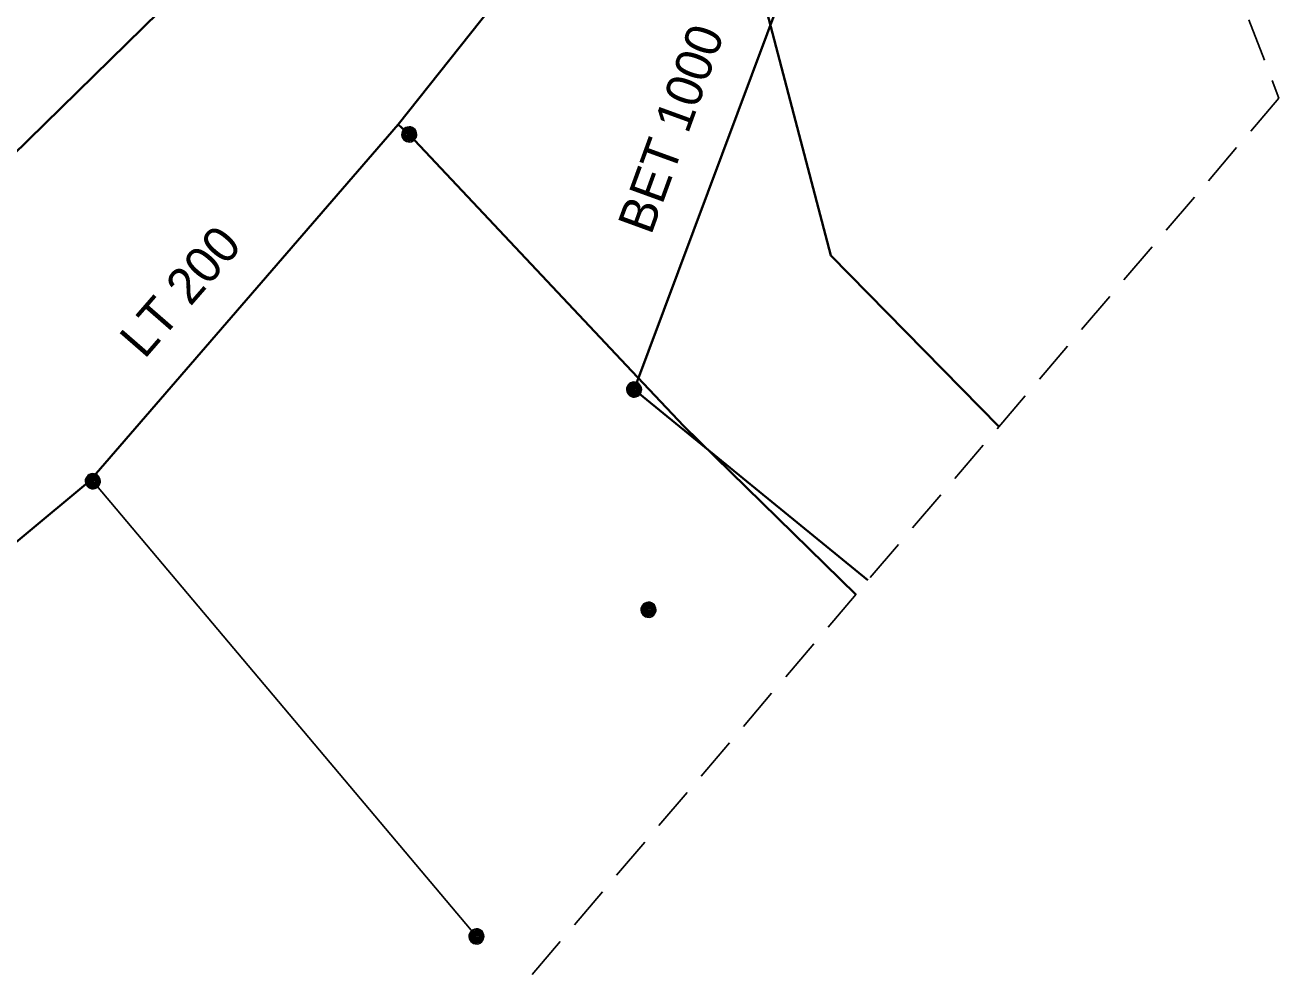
# Model space of a CAD drawing. Extents: x -867104 to -866746, y -1014489 to -1014255.
# Drawn here: x -866784.33 to -866746.24, y -1014389.22 to -1014360.49 of the extents above; entities that cross this region are included whole.
import ezdxf

# ---------------------------------------------------------------- set-up
doc = ezdxf.new("R2010")
doc.units = 0
doc.header["$LTSCALE"] = 0.44
doc.linetypes.add('MEDIUM_DASHED', pattern=[4.5, 3, -1.5])
for name, color, linetype, lineweight in [('1', 7, 'Continuous', 35), ('10', 7, 'Continuous', 13), ('12', 7, 'Continuous', 13), ('21', 7, 'Continuous', 35), ('3', 7, 'Continuous', 25), ('32', 7, 'Continuous', 13), ('62', 7, 'MEDIUM_DASHED', 25)]:
    doc.layers.add(name, color=color, linetype=linetype, lineweight=lineweight)

msp = doc.modelspace()

# ---------------------------------------------------------------- linework, layer by layer
at = {"layer": '1'}
for points in [[(-866752.928, -1014345.35), (-866767.662, -1014356.784), (-866772.99, -1014363.51), (-866782.36, -1014374.33), (-866829.29, -1014413.39)], [(-866763.454, -1014353.518), (-866763.39, -1014353.97), (-866759.847, -1014367.488), (-866754.744, -1014372.687)], [(-866772.99, -1014363.51), (-866772.66, -1014363.81), (-866765.9, -1014371), (-866764.32, -1014372.67), (-866759.089, -1014377.786)]]:
    msp.add_lwpolyline(points, dxfattribs=at)
at = {"layer": '10'}
for points in [[(-866770.385, -1014388.173), (-866770.391, -1014388.121), (-866770.408, -1014388.071), (-866770.437, -1014388.027), (-866770.474, -1014387.99), (-866770.519, -1014387.963), (-866770.569, -1014387.946), (-866770.622, -1014387.942), (-866770.674, -1014387.949), (-866770.723, -1014387.968), (-866770.766, -1014387.997), (-866770.802, -1014388.036), (-866770.828, -1014388.081), (-866770.844, -1014388.132), (-866770.847, -1014388.184), (-866770.839, -1014388.236), (-866770.819, -1014388.285), (-866770.788, -1014388.328), (-866770.749, -1014388.362), (-866770.703, -1014388.388), (-866770.652, -1014388.402), (-866770.599, -1014388.404), (-866770.548, -1014388.394), (-866770.5, -1014388.373), (-866770.457, -1014388.342), (-866770.423, -1014388.301), (-866770.399, -1014388.255), (-866770.387, -1014388.204)], [(-866770.415, -1014388.173), (-866770.421, -1014388.124), (-866770.438, -1014388.078), (-866770.466, -1014388.038), (-866770.503, -1014388.006), (-866770.547, -1014387.984), (-866770.595, -1014387.973), (-866770.644, -1014387.973), (-866770.691, -1014387.986), (-866770.734, -1014388.01), (-866770.77, -1014388.043), (-866770.797, -1014388.084), (-866770.813, -1014388.131), (-866770.817, -1014388.18), (-866770.81, -1014388.228), (-866770.791, -1014388.273), (-866770.761, -1014388.313), (-866770.723, -1014388.344), (-866770.679, -1014388.364), (-866770.631, -1014388.374), (-866770.582, -1014388.372), (-866770.535, -1014388.357), (-866770.492, -1014388.332), (-866770.458, -1014388.298), (-866770.432, -1014388.256), (-866770.418, -1014388.209)], [(-866770.445, -1014388.173), (-866770.451, -1014388.128), (-866770.468, -1014388.086), (-866770.496, -1014388.051), (-866770.532, -1014388.024), (-866770.574, -1014388.007), (-866770.619, -1014388.002), (-866770.664, -1014388.008), (-866770.705, -1014388.027), (-866770.74, -1014388.055), (-866770.767, -1014388.092), (-866770.783, -1014388.134), (-866770.787, -1014388.179), (-866770.78, -1014388.224), (-866770.761, -1014388.265), (-866770.732, -1014388.299), (-866770.695, -1014388.325), (-866770.652, -1014388.341), (-866770.607, -1014388.344), (-866770.562, -1014388.336), (-866770.522, -1014388.316), (-866770.488, -1014388.287), (-866770.462, -1014388.249), (-866770.448, -1014388.206)], [(-866770.475, -1014388.173), (-866770.48, -1014388.132), (-866770.498, -1014388.095), (-866770.525, -1014388.064), (-866770.56, -1014388.043), (-866770.6, -1014388.032), (-866770.641, -1014388.034), (-866770.68, -1014388.047), (-866770.714, -1014388.071), (-866770.739, -1014388.103), (-866770.754, -1014388.141), (-866770.757, -1014388.182), (-866770.749, -1014388.222), (-866770.729, -1014388.258), (-866770.7, -1014388.287), (-866770.663, -1014388.306), (-866770.623, -1014388.314), (-866770.582, -1014388.31), (-866770.544, -1014388.295), (-866770.512, -1014388.269), (-866770.489, -1014388.235), (-866770.476, -1014388.196)], [(-866770.505, -1014388.173), (-866770.51, -1014388.137), (-866770.528, -1014388.105), (-866770.554, -1014388.08), (-866770.588, -1014388.065), (-866770.624, -1014388.062), (-866770.659, -1014388.07), (-866770.69, -1014388.09), (-866770.713, -1014388.118), (-866770.726, -1014388.152), (-866770.726, -1014388.189), (-866770.715, -1014388.224), (-866770.694, -1014388.253), (-866770.664, -1014388.274), (-866770.629, -1014388.284), (-866770.592, -1014388.282), (-866770.558, -1014388.268), (-866770.531, -1014388.245), (-866770.512, -1014388.213), (-866770.505, -1014388.178)], [(-866770.535, -1014388.173), (-866770.54, -1014388.142), (-866770.557, -1014388.116), (-866770.583, -1014388.099), (-866770.613, -1014388.092), (-866770.644, -1014388.096), (-866770.671, -1014388.113), (-866770.689, -1014388.137), (-866770.697, -1014388.168), (-866770.693, -1014388.198), (-866770.678, -1014388.226), (-866770.654, -1014388.245), (-866770.624, -1014388.254), (-866770.593, -1014388.251), (-866770.565, -1014388.237), (-866770.545, -1014388.213), (-866770.535, -1014388.184)], [(-866770.565, -1014388.173), (-866770.57, -1014388.149), (-866770.587, -1014388.131), (-866770.61, -1014388.122), (-866770.634, -1014388.125), (-866770.655, -1014388.139), (-866770.666, -1014388.161), (-866770.666, -1014388.186), (-866770.654, -1014388.207), (-866770.634, -1014388.221), (-866770.609, -1014388.224), (-866770.586, -1014388.215), (-866770.57, -1014388.197)], [(-866770.595, -1014388.173), (-866770.6, -1014388.158), (-866770.615, -1014388.152), (-866770.63, -1014388.156), (-866770.637, -1014388.17), (-866770.633, -1014388.185), (-866770.62, -1014388.194), (-866770.605, -1014388.191), (-866770.595, -1014388.179)]]:
    msp.add_lwpolyline(points, close=True, dxfattribs=at)
at = {"layer": '12'}
for points in [[(-866772.428, -1014363.81), (-866772.434, -1014363.758), (-866772.451, -1014363.708), (-866772.48, -1014363.664), (-866772.517, -1014363.627), (-866772.562, -1014363.6), (-866772.612, -1014363.583), (-866772.665, -1014363.579), (-866772.717, -1014363.586), (-866772.766, -1014363.605), (-866772.809, -1014363.634), (-866772.845, -1014363.673), (-866772.871, -1014363.718), (-866772.887, -1014363.769), (-866772.89, -1014363.821), (-866772.882, -1014363.873), (-866772.862, -1014363.922), (-866772.831, -1014363.965), (-866772.792, -1014363.999), (-866772.746, -1014364.025), (-866772.695, -1014364.039), (-866772.642, -1014364.041), (-866772.591, -1014364.031), (-866772.543, -1014364.01), (-866772.5, -1014363.979), (-866772.466, -1014363.938), (-866772.442, -1014363.892), (-866772.429, -1014363.841)], [(-866772.458, -1014363.81), (-866772.464, -1014363.761), (-866772.481, -1014363.715), (-866772.509, -1014363.675), (-866772.546, -1014363.643), (-866772.59, -1014363.621), (-866772.638, -1014363.61), (-866772.687, -1014363.61), (-866772.733, -1014363.623), (-866772.777, -1014363.647), (-866772.813, -1014363.68), (-866772.84, -1014363.721), (-866772.856, -1014363.768), (-866772.86, -1014363.817), (-866772.853, -1014363.865), (-866772.834, -1014363.91), (-866772.804, -1014363.95), (-866772.766, -1014363.981), (-866772.722, -1014364.001), (-866772.674, -1014364.011), (-866772.625, -1014364.009), (-866772.578, -1014363.994), (-866772.535, -1014363.969), (-866772.5, -1014363.935), (-866772.475, -1014363.893), (-866772.461, -1014363.846)], [(-866772.488, -1014363.81), (-866772.494, -1014363.765), (-866772.511, -1014363.723), (-866772.539, -1014363.688), (-866772.575, -1014363.661), (-866772.617, -1014363.644), (-866772.662, -1014363.639), (-866772.706, -1014363.645), (-866772.748, -1014363.664), (-866772.782, -1014363.692), (-866772.809, -1014363.729), (-866772.826, -1014363.771), (-866772.83, -1014363.816), (-866772.823, -1014363.861), (-866772.804, -1014363.902), (-866772.775, -1014363.936), (-866772.738, -1014363.962), (-866772.695, -1014363.978), (-866772.65, -1014363.981), (-866772.605, -1014363.973), (-866772.565, -1014363.953), (-866772.531, -1014363.924), (-866772.505, -1014363.886), (-866772.491, -1014363.843)], [(-866772.518, -1014363.81), (-866772.522, -1014363.769), (-866772.541, -1014363.732), (-866772.568, -1014363.701), (-866772.603, -1014363.68), (-866772.643, -1014363.669), (-866772.684, -1014363.671), (-866772.723, -1014363.684), (-866772.757, -1014363.708), (-866772.782, -1014363.74), (-866772.797, -1014363.778), (-866772.799, -1014363.819), (-866772.792, -1014363.859), (-866772.772, -1014363.895), (-866772.743, -1014363.924), (-866772.706, -1014363.943), (-866772.666, -1014363.951), (-866772.625, -1014363.947), (-866772.587, -1014363.932), (-866772.554, -1014363.906), (-866772.532, -1014363.872), (-866772.519, -1014363.833)], [(-866772.548, -1014363.81), (-866772.553, -1014363.774), (-866772.571, -1014363.742), (-866772.597, -1014363.717), (-866772.63, -1014363.702), (-866772.667, -1014363.699), (-866772.701, -1014363.707), (-866772.733, -1014363.727), (-866772.755, -1014363.755), (-866772.769, -1014363.789), (-866772.769, -1014363.826), (-866772.758, -1014363.861), (-866772.737, -1014363.89), (-866772.706, -1014363.911), (-866772.672, -1014363.921), (-866772.635, -1014363.919), (-866772.601, -1014363.905), (-866772.574, -1014363.882), (-866772.554, -1014363.85), (-866772.548, -1014363.815)], [(-866772.578, -1014363.81), (-866772.583, -1014363.779), (-866772.6, -1014363.753), (-866772.625, -1014363.736), (-866772.656, -1014363.729), (-866772.687, -1014363.733), (-866772.714, -1014363.75), (-866772.732, -1014363.774), (-866772.74, -1014363.805), (-866772.736, -1014363.835), (-866772.721, -1014363.863), (-866772.696, -1014363.882), (-866772.667, -1014363.891), (-866772.636, -1014363.888), (-866772.608, -1014363.874), (-866772.588, -1014363.85), (-866772.578, -1014363.821)], [(-866772.608, -1014363.81), (-866772.613, -1014363.786), (-866772.63, -1014363.768), (-866772.652, -1014363.759), (-866772.677, -1014363.762), (-866772.698, -1014363.776), (-866772.709, -1014363.798), (-866772.709, -1014363.823), (-866772.696, -1014363.844), (-866772.677, -1014363.858), (-866772.652, -1014363.861), (-866772.629, -1014363.852), (-866772.613, -1014363.834)], [(-866772.638, -1014363.81), (-866772.643, -1014363.795), (-866772.657, -1014363.789), (-866772.673, -1014363.793), (-866772.679, -1014363.807), (-866772.676, -1014363.822), (-866772.663, -1014363.831), (-866772.647, -1014363.828), (-866772.638, -1014363.816)], [(-866782.041, -1014374.344), (-866782.047, -1014374.292), (-866782.064, -1014374.242), (-866782.093, -1014374.198), (-866782.13, -1014374.161), (-866782.175, -1014374.134), (-866782.225, -1014374.117), (-866782.278, -1014374.113), (-866782.33, -1014374.12), (-866782.379, -1014374.139), (-866782.422, -1014374.168), (-866782.458, -1014374.207), (-866782.484, -1014374.252), (-866782.5, -1014374.303), (-866782.503, -1014374.355), (-866782.495, -1014374.407), (-866782.475, -1014374.456), (-866782.444, -1014374.499), (-866782.405, -1014374.533), (-866782.359, -1014374.559), (-866782.308, -1014374.573), (-866782.255, -1014374.575), (-866782.204, -1014374.565), (-866782.156, -1014374.544), (-866782.113, -1014374.513), (-866782.079, -1014374.472), (-866782.055, -1014374.426), (-866782.043, -1014374.375)], [(-866782.071, -1014374.344), (-866782.077, -1014374.295), (-866782.094, -1014374.249), (-866782.122, -1014374.209), (-866782.159, -1014374.177), (-866782.203, -1014374.155), (-866782.251, -1014374.144), (-866782.3, -1014374.144), (-866782.347, -1014374.157), (-866782.39, -1014374.181), (-866782.426, -1014374.214), (-866782.453, -1014374.255), (-866782.469, -1014374.302), (-866782.473, -1014374.351), (-866782.466, -1014374.399), (-866782.447, -1014374.444), (-866782.417, -1014374.484), (-866782.379, -1014374.515), (-866782.335, -1014374.535), (-866782.287, -1014374.545), (-866782.238, -1014374.543), (-866782.191, -1014374.528), (-866782.148, -1014374.503), (-866782.114, -1014374.469), (-866782.088, -1014374.427), (-866782.074, -1014374.38)], [(-866782.101, -1014374.344), (-866782.107, -1014374.299), (-866782.124, -1014374.257), (-866782.152, -1014374.222), (-866782.188, -1014374.195), (-866782.23, -1014374.178), (-866782.275, -1014374.173), (-866782.32, -1014374.179), (-866782.361, -1014374.198), (-866782.396, -1014374.226), (-866782.423, -1014374.263), (-866782.439, -1014374.305), (-866782.443, -1014374.35), (-866782.436, -1014374.395), (-866782.417, -1014374.436), (-866782.388, -1014374.47), (-866782.351, -1014374.496), (-866782.308, -1014374.512), (-866782.263, -1014374.515), (-866782.218, -1014374.507), (-866782.178, -1014374.487), (-866782.144, -1014374.458), (-866782.118, -1014374.42), (-866782.104, -1014374.377)], [(-866782.131, -1014374.344), (-866782.136, -1014374.303), (-866782.154, -1014374.266), (-866782.181, -1014374.235), (-866782.216, -1014374.214), (-866782.256, -1014374.203), (-866782.297, -1014374.205), (-866782.336, -1014374.218), (-866782.37, -1014374.242), (-866782.395, -1014374.274), (-866782.41, -1014374.312), (-866782.413, -1014374.353), (-866782.405, -1014374.393), (-866782.385, -1014374.429), (-866782.356, -1014374.458), (-866782.319, -1014374.477), (-866782.279, -1014374.485), (-866782.238, -1014374.481), (-866782.2, -1014374.466), (-866782.168, -1014374.44), (-866782.145, -1014374.406), (-866782.132, -1014374.367)], [(-866782.161, -1014374.344), (-866782.166, -1014374.308), (-866782.184, -1014374.276), (-866782.21, -1014374.251), (-866782.244, -1014374.236), (-866782.28, -1014374.233), (-866782.315, -1014374.241), (-866782.346, -1014374.261), (-866782.369, -1014374.289), (-866782.382, -1014374.323), (-866782.382, -1014374.36), (-866782.371, -1014374.395), (-866782.35, -1014374.424), (-866782.32, -1014374.445), (-866782.285, -1014374.455), (-866782.248, -1014374.453), (-866782.214, -1014374.439), (-866782.187, -1014374.416), (-866782.168, -1014374.384), (-866782.161, -1014374.349)], [(-866782.191, -1014374.344), (-866782.196, -1014374.313), (-866782.213, -1014374.287), (-866782.239, -1014374.27), (-866782.269, -1014374.263), (-866782.3, -1014374.267), (-866782.327, -1014374.284), (-866782.345, -1014374.308), (-866782.353, -1014374.339), (-866782.349, -1014374.369), (-866782.334, -1014374.397), (-866782.309, -1014374.416), (-866782.28, -1014374.425), (-866782.249, -1014374.422), (-866782.221, -1014374.408), (-866782.201, -1014374.384), (-866782.191, -1014374.355)], [(-866782.221, -1014374.344), (-866782.226, -1014374.32), (-866782.243, -1014374.302), (-866782.266, -1014374.293), (-866782.29, -1014374.296), (-866782.311, -1014374.31), (-866782.322, -1014374.332), (-866782.322, -1014374.357), (-866782.309, -1014374.378), (-866782.29, -1014374.392), (-866782.265, -1014374.395), (-866782.242, -1014374.386), (-866782.226, -1014374.368)], [(-866782.251, -1014374.344), (-866782.256, -1014374.329), (-866782.271, -1014374.323), (-866782.286, -1014374.327), (-866782.293, -1014374.341), (-866782.289, -1014374.356), (-866782.276, -1014374.365), (-866782.261, -1014374.362), (-866782.251, -1014374.35)]]:
    msp.add_lwpolyline(points, close=True, dxfattribs=at)
at = {"layer": '21'}
for p, q in [((-866771.588, -1014351.589), (-866821.947, -1014400.93)), ((-866765.827, -1014371.56), (-866759.561, -1014354.793)), ((-866758.722, -1014377.355), (-866765.827, -1014371.56))]:
    msp.add_line(p, q, dxfattribs=at)
at = {"layer": '3'}
msp.add_line((-866782.321, -1014374.285), (-866770.616, -1014388.173), dxfattribs=at)
at = {"layer": '32'}
for points in [[(-866765.596, -1014371.56), (-866765.602, -1014371.508), (-866765.619, -1014371.458), (-866765.648, -1014371.414), (-866765.685, -1014371.377), (-866765.73, -1014371.35), (-866765.78, -1014371.333), (-866765.833, -1014371.329), (-866765.885, -1014371.336), (-866765.934, -1014371.355), (-866765.977, -1014371.384), (-866766.013, -1014371.423), (-866766.039, -1014371.468), (-866766.055, -1014371.519), (-866766.058, -1014371.571), (-866766.05, -1014371.623), (-866766.03, -1014371.672), (-866765.999, -1014371.715), (-866765.96, -1014371.749), (-866765.914, -1014371.775), (-866765.863, -1014371.789), (-866765.81, -1014371.791), (-866765.759, -1014371.781), (-866765.711, -1014371.76), (-866765.668, -1014371.729), (-866765.634, -1014371.688), (-866765.61, -1014371.642), (-866765.598, -1014371.591)], [(-866765.626, -1014371.56), (-866765.632, -1014371.511), (-866765.649, -1014371.465), (-866765.677, -1014371.425), (-866765.714, -1014371.393), (-866765.758, -1014371.371), (-866765.806, -1014371.36), (-866765.855, -1014371.36), (-866765.902, -1014371.373), (-866765.945, -1014371.397), (-866765.981, -1014371.43), (-866766.008, -1014371.471), (-866766.024, -1014371.518), (-866766.028, -1014371.567), (-866766.021, -1014371.615), (-866766.002, -1014371.66), (-866765.972, -1014371.7), (-866765.934, -1014371.731), (-866765.89, -1014371.751), (-866765.842, -1014371.761), (-866765.793, -1014371.759), (-866765.746, -1014371.744), (-866765.703, -1014371.719), (-866765.669, -1014371.685), (-866765.643, -1014371.643), (-866765.629, -1014371.596)], [(-866765.656, -1014371.56), (-866765.662, -1014371.515), (-866765.679, -1014371.473), (-866765.707, -1014371.438), (-866765.743, -1014371.411), (-866765.785, -1014371.394), (-866765.83, -1014371.389), (-866765.875, -1014371.395), (-866765.916, -1014371.414), (-866765.951, -1014371.442), (-866765.978, -1014371.479), (-866765.994, -1014371.521), (-866765.998, -1014371.566), (-866765.991, -1014371.611), (-866765.972, -1014371.652), (-866765.943, -1014371.686), (-866765.906, -1014371.712), (-866765.863, -1014371.728), (-866765.818, -1014371.731), (-866765.773, -1014371.723), (-866765.733, -1014371.703), (-866765.699, -1014371.674), (-866765.673, -1014371.636), (-866765.659, -1014371.593)], [(-866765.686, -1014371.56), (-866765.691, -1014371.519), (-866765.709, -1014371.482), (-866765.736, -1014371.451), (-866765.771, -1014371.43), (-866765.811, -1014371.419), (-866765.852, -1014371.421), (-866765.891, -1014371.434), (-866765.925, -1014371.458), (-866765.95, -1014371.49), (-866765.965, -1014371.528), (-866765.968, -1014371.569), (-866765.96, -1014371.609), (-866765.94, -1014371.645), (-866765.911, -1014371.674), (-866765.874, -1014371.693), (-866765.834, -1014371.701), (-866765.793, -1014371.697), (-866765.755, -1014371.682), (-866765.723, -1014371.656), (-866765.7, -1014371.622), (-866765.687, -1014371.583)], [(-866765.716, -1014371.56), (-866765.721, -1014371.524), (-866765.739, -1014371.492), (-866765.765, -1014371.467), (-866765.799, -1014371.452), (-866765.835, -1014371.449), (-866765.87, -1014371.457), (-866765.901, -1014371.477), (-866765.924, -1014371.505), (-866765.937, -1014371.539), (-866765.937, -1014371.576), (-866765.926, -1014371.611), (-866765.905, -1014371.64), (-866765.875, -1014371.661), (-866765.84, -1014371.671), (-866765.803, -1014371.669), (-866765.769, -1014371.655), (-866765.742, -1014371.632), (-866765.723, -1014371.6), (-866765.716, -1014371.565)], [(-866765.746, -1014371.56), (-866765.751, -1014371.529), (-866765.768, -1014371.503), (-866765.794, -1014371.486), (-866765.824, -1014371.479), (-866765.855, -1014371.483), (-866765.882, -1014371.5), (-866765.9, -1014371.524), (-866765.908, -1014371.555), (-866765.904, -1014371.585), (-866765.889, -1014371.613), (-866765.865, -1014371.632), (-866765.835, -1014371.641), (-866765.804, -1014371.638), (-866765.776, -1014371.624), (-866765.756, -1014371.6), (-866765.746, -1014371.571)], [(-866765.776, -1014371.56), (-866765.781, -1014371.536), (-866765.798, -1014371.518), (-866765.821, -1014371.509), (-866765.845, -1014371.512), (-866765.866, -1014371.526), (-866765.877, -1014371.548), (-866765.877, -1014371.573), (-866765.865, -1014371.594), (-866765.845, -1014371.608), (-866765.82, -1014371.611), (-866765.797, -1014371.602), (-866765.781, -1014371.584)], [(-866765.806, -1014371.56), (-866765.811, -1014371.545), (-866765.826, -1014371.539), (-866765.841, -1014371.543), (-866765.848, -1014371.557), (-866765.844, -1014371.572), (-866765.831, -1014371.581), (-866765.816, -1014371.578), (-866765.806, -1014371.566)], [(-866765.159, -1014378.25), (-866765.165, -1014378.198), (-866765.182, -1014378.148), (-866765.211, -1014378.104), (-866765.248, -1014378.067), (-866765.293, -1014378.04), (-866765.343, -1014378.023), (-866765.396, -1014378.019), (-866765.448, -1014378.026), (-866765.497, -1014378.045), (-866765.54, -1014378.074), (-866765.576, -1014378.113), (-866765.602, -1014378.158), (-866765.618, -1014378.209), (-866765.621, -1014378.261), (-866765.613, -1014378.313), (-866765.593, -1014378.362), (-866765.562, -1014378.405), (-866765.523, -1014378.439), (-866765.477, -1014378.465), (-866765.426, -1014378.479), (-866765.373, -1014378.481), (-866765.322, -1014378.471), (-866765.274, -1014378.45), (-866765.231, -1014378.419), (-866765.197, -1014378.378), (-866765.173, -1014378.332), (-866765.161, -1014378.281)], [(-866765.189, -1014378.25), (-866765.195, -1014378.201), (-866765.212, -1014378.155), (-866765.24, -1014378.115), (-866765.277, -1014378.083), (-866765.321, -1014378.061), (-866765.369, -1014378.05), (-866765.418, -1014378.05), (-866765.465, -1014378.063), (-866765.508, -1014378.087), (-866765.544, -1014378.12), (-866765.571, -1014378.161), (-866765.587, -1014378.208), (-866765.591, -1014378.257), (-866765.584, -1014378.305), (-866765.565, -1014378.35), (-866765.535, -1014378.39), (-866765.497, -1014378.421), (-866765.453, -1014378.441), (-866765.405, -1014378.451), (-866765.356, -1014378.449), (-866765.309, -1014378.434), (-866765.266, -1014378.409), (-866765.232, -1014378.375), (-866765.206, -1014378.333), (-866765.192, -1014378.286)], [(-866765.219, -1014378.25), (-866765.225, -1014378.205), (-866765.242, -1014378.163), (-866765.27, -1014378.128), (-866765.306, -1014378.101), (-866765.348, -1014378.084), (-866765.393, -1014378.079), (-866765.438, -1014378.085), (-866765.479, -1014378.104), (-866765.514, -1014378.132), (-866765.541, -1014378.169), (-866765.557, -1014378.211), (-866765.561, -1014378.256), (-866765.554, -1014378.301), (-866765.535, -1014378.342), (-866765.506, -1014378.376), (-866765.469, -1014378.402), (-866765.426, -1014378.418), (-866765.381, -1014378.421), (-866765.336, -1014378.413), (-866765.296, -1014378.393), (-866765.262, -1014378.364), (-866765.236, -1014378.326), (-866765.222, -1014378.283)], [(-866765.249, -1014378.25), (-866765.254, -1014378.209), (-866765.272, -1014378.172), (-866765.299, -1014378.141), (-866765.334, -1014378.12), (-866765.374, -1014378.109), (-866765.415, -1014378.111), (-866765.454, -1014378.124), (-866765.488, -1014378.148), (-866765.513, -1014378.18), (-866765.528, -1014378.218), (-866765.531, -1014378.259), (-866765.523, -1014378.299), (-866765.503, -1014378.335), (-866765.474, -1014378.364), (-866765.437, -1014378.383), (-866765.397, -1014378.391), (-866765.356, -1014378.387), (-866765.318, -1014378.372), (-866765.286, -1014378.346), (-866765.263, -1014378.312), (-866765.25, -1014378.273)], [(-866765.279, -1014378.25), (-866765.284, -1014378.214), (-866765.302, -1014378.182), (-866765.328, -1014378.157), (-866765.362, -1014378.142), (-866765.398, -1014378.139), (-866765.433, -1014378.147), (-866765.464, -1014378.167), (-866765.487, -1014378.195), (-866765.5, -1014378.229), (-866765.5, -1014378.266), (-866765.489, -1014378.301), (-866765.468, -1014378.33), (-866765.438, -1014378.351), (-866765.403, -1014378.361), (-866765.366, -1014378.359), (-866765.332, -1014378.345), (-866765.305, -1014378.322), (-866765.286, -1014378.29), (-866765.279, -1014378.255)], [(-866765.309, -1014378.25), (-866765.314, -1014378.219), (-866765.331, -1014378.193), (-866765.357, -1014378.176), (-866765.387, -1014378.169), (-866765.418, -1014378.173), (-866765.445, -1014378.19), (-866765.463, -1014378.214), (-866765.471, -1014378.245), (-866765.467, -1014378.275), (-866765.452, -1014378.303), (-866765.428, -1014378.322), (-866765.398, -1014378.331), (-866765.367, -1014378.328), (-866765.339, -1014378.314), (-866765.319, -1014378.29), (-866765.309, -1014378.261)], [(-866765.339, -1014378.25), (-866765.344, -1014378.226), (-866765.361, -1014378.208), (-866765.384, -1014378.199), (-866765.408, -1014378.202), (-866765.429, -1014378.216), (-866765.44, -1014378.238), (-866765.44, -1014378.263), (-866765.428, -1014378.284), (-866765.408, -1014378.298), (-866765.383, -1014378.301), (-866765.36, -1014378.292), (-866765.344, -1014378.274)], [(-866765.369, -1014378.25), (-866765.374, -1014378.235), (-866765.389, -1014378.229), (-866765.404, -1014378.233), (-866765.411, -1014378.247), (-866765.407, -1014378.262), (-866765.394, -1014378.271), (-866765.379, -1014378.268), (-866765.369, -1014378.256)]]:
    msp.add_lwpolyline(points, close=True, dxfattribs=at)
at = {"layer": '62'}
msp.add_lwpolyline([(-867100.742, -1014391.242), (-867092.704, -1014271.063), (-867058.137, -1014262.221), (-866832.652, -1014254.584), (-866798.889, -1014276.691), (-866769.95, -1014301.209), (-866746.236, -1014362.705), (-866806.526, -1014433.445), (-866883.697, -1014488.912), (-866958.859, -1014435.455)], close=True, dxfattribs=at)

# ---------------------------------------------------------------- texts
at = {"layer": '1'}
for s, rotation, p in [('BET 1000', 70, (-866765.312, -1014366.895)), ('LT 200', 49, (-866780.704, -1014370.661))]:
    msp.add_text(s, height=1.1, rotation=rotation, dxfattribs=at).set_placement(p)

doc.saveas('drawing.dxf')
